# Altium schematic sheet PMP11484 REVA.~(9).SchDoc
size 431 x 279 mm; Date: Not shown in title block; ApprovedBy: Not shown in title block; CheckedBy: Not shown in title block; Author: Not shown in title block; CompanyName: Not shown in title block; Engineer: Not shown in title block; Organization: Not shown in title block; Address1: Not shown in title block; Address2: Not shown in title block; Address3: Not shown in title block; Address4: Not shown in title block; DocumentNumber: 1; Revision: Use project parameter SCH_Rev; SheetNumber: 1; SheetTotal: 1; PageSetup: Record=PageOptions¦CenterHorizontal=True¦CenterVertical=True¦PrintScale=1.00¦XCorrection=1.00¦YCorrection=1.00¦PrintKind=0¦BorderSize=5000000¦LeftOffset=0¦BottomOffset=0¦Orientation=2¦PaperLength=1000¦PaperWidth=1000¦Scale=100¦PaperSource=15¦PrintQuality=600¦MediaType=1¦DitherType=10¦PaperKind=Letter¦PrintScaleMode=1
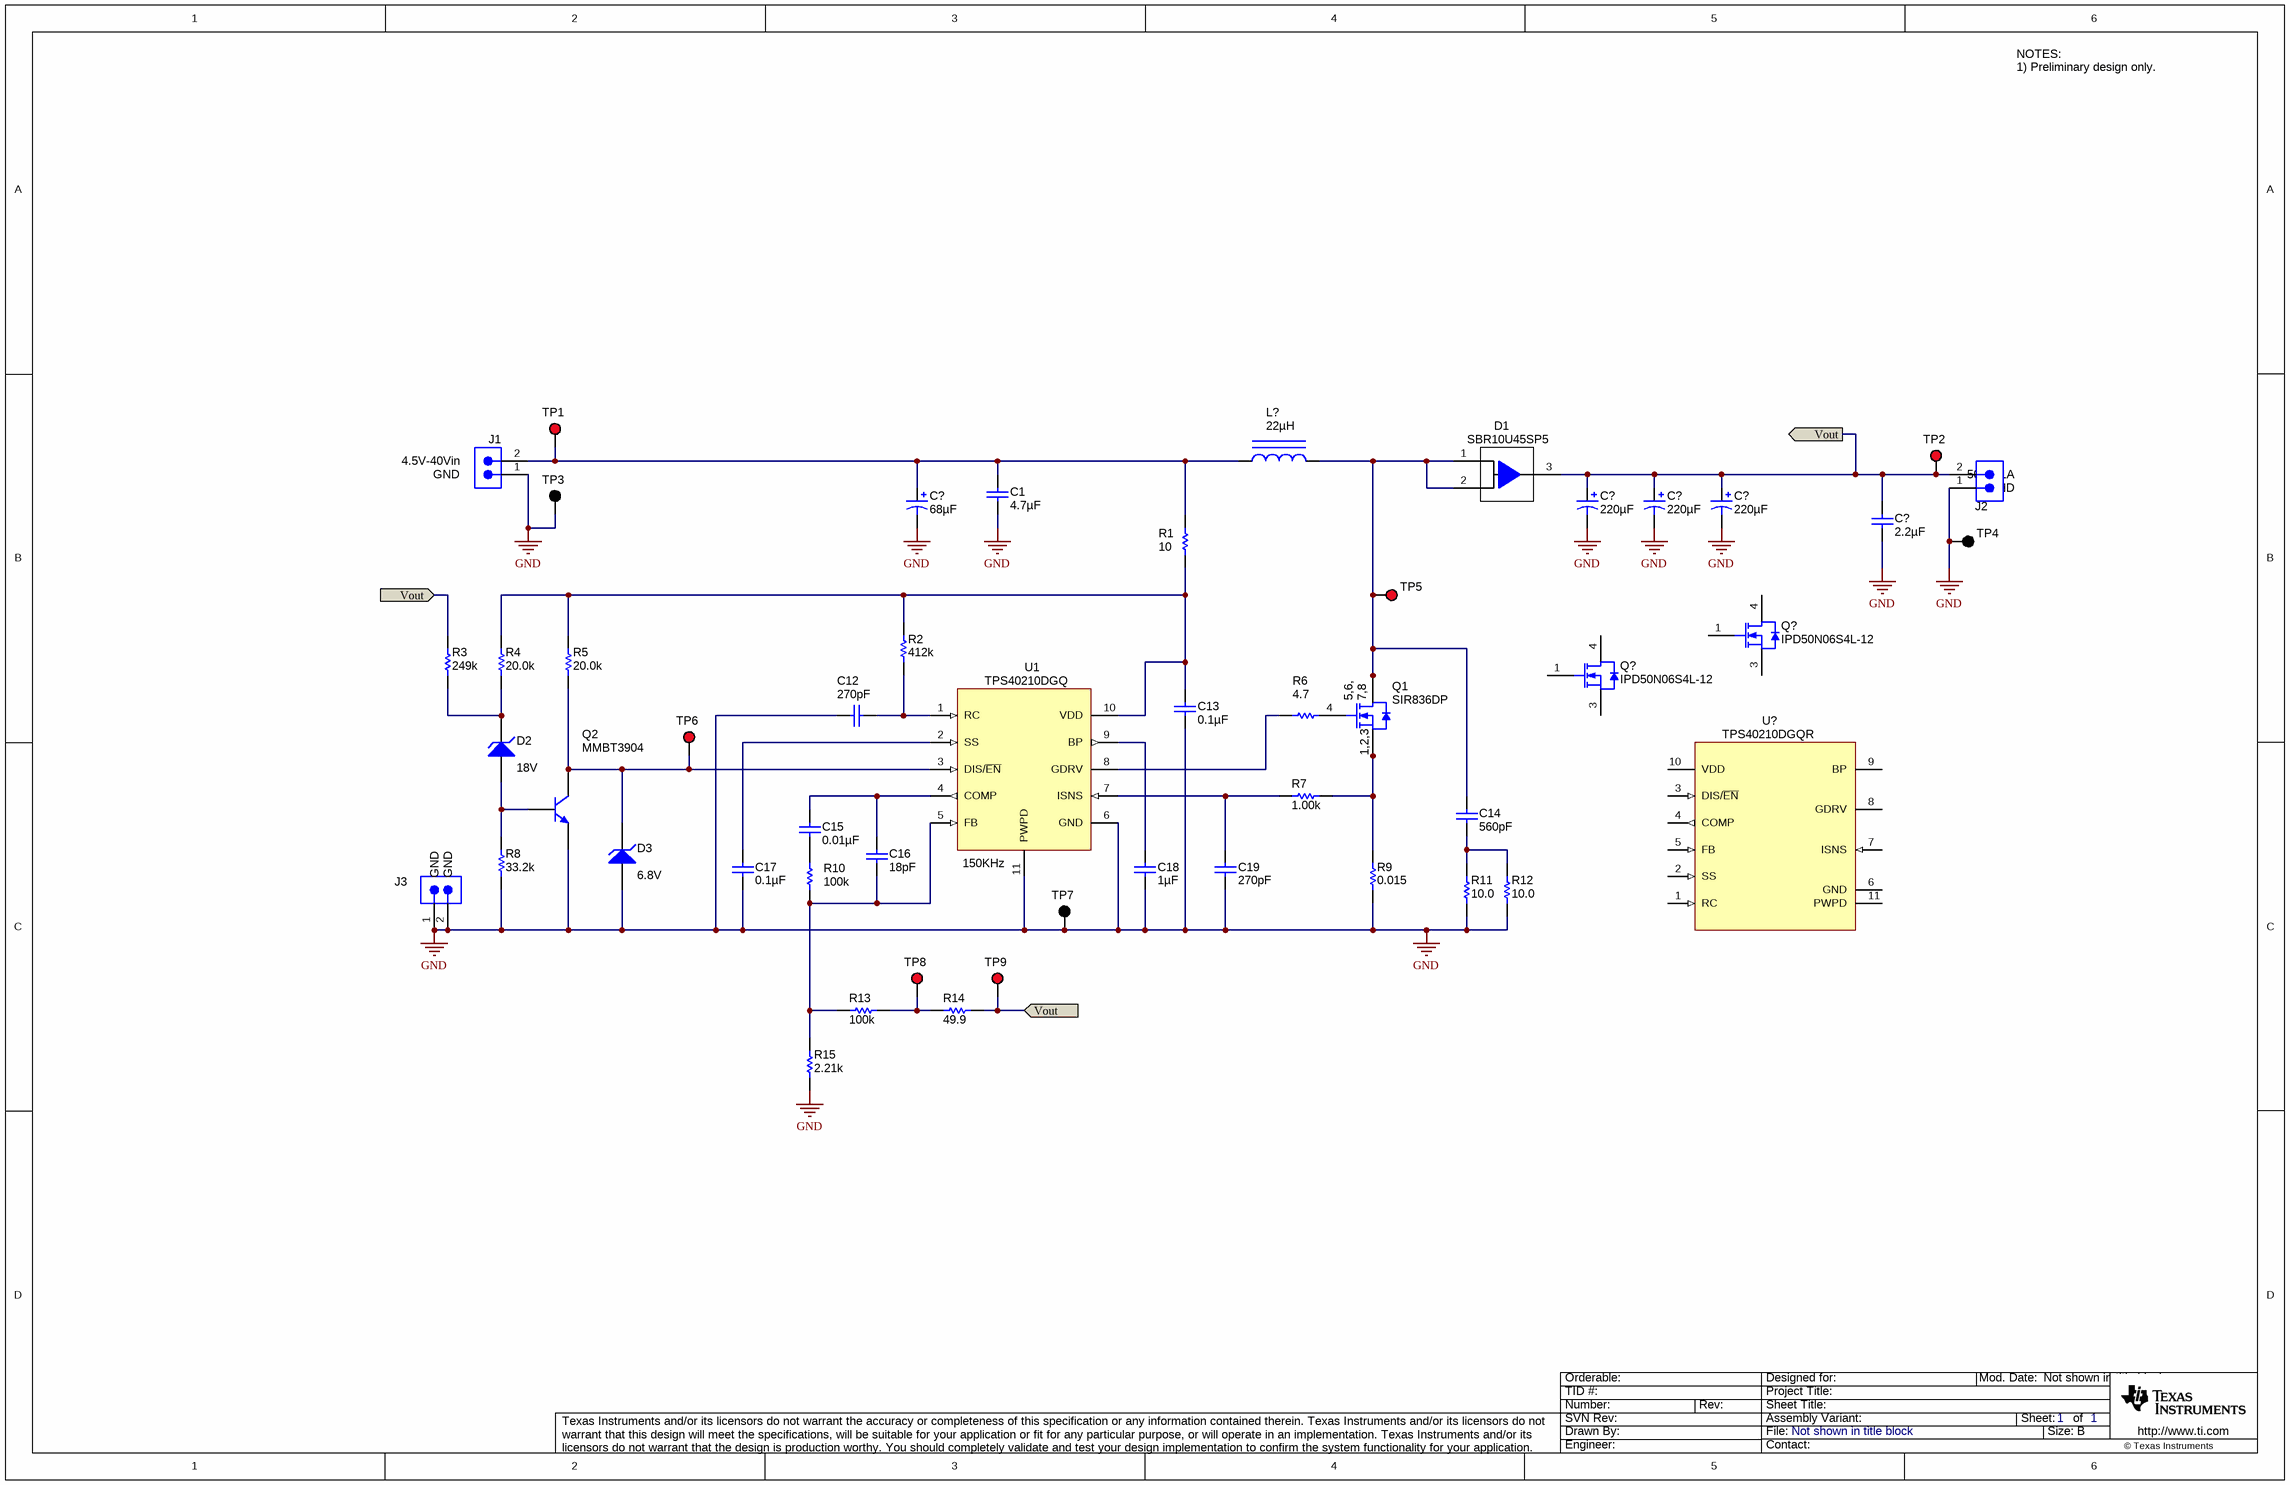
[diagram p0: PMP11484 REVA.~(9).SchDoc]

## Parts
(Parts that share a designator on the sheet are numbered #1, #2 ... from top to bottom, then left to right.)
C1  ValueDisplayed: 4.7µF  [1210]  (hidden comment: C3225X7R1H475M250AB)
C12  ValueDisplayed: 270pF  [0603]  (hidden comment: GRM1885C1H271JA01D)
C13  ValueDisplayed: 0.1µF  [0603]  (hidden comment: C1608X7R1H104K)
C14  ValueDisplayed: 560pF  [0603]  (hidden comment: C1608C0G1H561J)
C15  ValueDisplayed: 0.01µF  [0603]  (hidden comment: C1608X7R1H103K)
C16  ValueDisplayed: 18pF  [0603]  (hidden comment: C1608C0G1H180J)
C17  ValueDisplayed: 0.1µF  [0603]  (hidden comment: C1608X7R1H104K)
C18  ValueDisplayed: 1µF  [0603]  (hidden comment: C1608X7R1C105K)
C19  ValueDisplayed: 270pF  [0603]  (hidden comment: GRM1885C1H271JA01D)
C?#1  ValueDisplayed: 68µF  [SM_RADIAL_8MM]  (hidden comment: EEHZA1H680P)
C?#2  ValueDisplayed: 220µF  [BT_1250x2500]  (hidden comment: UBT1K221MHD1TO)
C?#3  ValueDisplayed: 220µF  [BT_1250x2500]  (hidden comment: UBT1K221MHD1TO)
C?#4  ValueDisplayed: 220µF  [BT_1250x2500]  (hidden comment: UBT1K221MHD1TO)
C?#5  ValueDisplayed: 2.2µF  [1210]  (hidden comment: GRM32ER72A225KA35L)
D1  SBR10U45SP5  [PowerDI5]
D2  value 18V  [SOD-123]  (hidden comment: MMSZ5248B)
D3  value 6.8V  [SOD-123]  (hidden comment: MMSZ5235B)
J1  ED555/2DS  [TERM_BLK_ED555-2DS]  (value not drawn)
J2  ED555/2DS  [TERM_BLK_ED555-2DS]  (value not drawn)
J3  PEC02SAAN  [CONN_PEC02SAAN]  (value not drawn)
L?  ValueDisplayed: 22µH  [IHLP8787MZ]  (hidden comment: IHLP8787MZER220M5A)
Q1  SIR836DP  [PowerPAK_SO-8]
Q2  MMBT3904  [SOT-23]
Q?#1  IPD50N06S4L-12  [DPAK]
Q?#2  IPD50N06S4L-12  [DPAK]
R1  value 10  [0603]  (hidden comment: CRCW060310R0JNEA)
R2  ValueDisplayed: 412k  [0603]  (hidden comment: CRCW0603412KFKEA)
R3  value 249k  [0603]  (hidden comment: CRCW0603249KFKEA)
R4  value 20.0k  [0603]  (hidden comment: CRCW060320K0FKEA)
R5  value 20.0k  [0603]  (hidden comment: CRCW060320K0FKEA)
R6  value 4.7  [0603]  (hidden comment: CRCW06034R70JNEA)
R7  value 1.00k  [0603]  (hidden comment: CRCW06031K00FKEA)
R8  value 33.2k  [0603]  (hidden comment: CRCW060333K2FKEA)
R9  value 0.015  [1206]  (hidden comment: CSR1206FK15L0)
R10  value 100k  [0603]  (hidden comment: CRCW0603100KFKEA)
R11  value 10.0  [1206]  (hidden comment: CRCW120610R0FKEA)
R12  value 10.0  [1206]  (hidden comment: CRCW120610R0FKEA)
R13  value 100k  [0603]  (hidden comment: CRCW0603100KFKEA)
R14  value 49.9  [0603]  (hidden comment: CRCW060349R9FKEA)
R15  value 2.21k  [0603]  (hidden comment: CRCW06032K21FKEA)
TP1  5000  [Keystone5000]  (value not drawn)
TP2  5000  [Keystone5000]  (value not drawn)
TP3  5001  [Keystone5001]  (value not drawn)
TP4  5001  [Keystone5001]  (value not drawn)
TP5  5000  [Keystone5000]  (value not drawn)
TP6  5000  [Keystone5000]  (value not drawn)
TP7  5001  [Keystone5001]  (value not drawn)
TP8  5000  [Keystone5000]  (value not drawn)
TP9  5000  [Keystone5000]  (value not drawn)
U1  TPS40210DGQ  [DGQ0010D_N]
U?  TPS40210DGQR  [DGQ0010D_N]

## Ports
Vout

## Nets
GND: C1.1 C12.1 C13.2 C17.2 C18.2 C19.2 C?#1.2(-) C?#2.2(-) C?#3.2(-) C?#4.2(-) C?#5.2 D3.2(A) J1.1 J2.1 J3.1 J3.2 Q2.2(E) R8.1 R9.1 R11.1 R12.1 R15.1 TP3.1 TP4.1 TP7.1 U1.6(GND) U1.11(PWPD)
Vout: C?#2.1(+) C?#3.1(+) C?#4.1(+) C?#5.1 D1.3(K) J2.2 R3.2 R14.1 TP2.1 TP9.1 ; port Vout
NetC1_2: C1.2 C?#1.1(+) J1.2 L?.1 R1.2 TP1.1
NetC12_2: C12.2 R2.1 U1.1(RC)
NetC13_1: C13.1 R1.1 R2.2 R4.2 R5.2 U1.10(VDD)
NetC14_1: C14.1 R11.2 R12.2
NetC14_2: C14.2 D1.1(A) D1.2(A) L?.2 Q1.5(D) Q1.6(D) Q1.7(D) Q1.8(D) Q1.9(D) TP5.1
NetC15_1: C15.1 R10.1
NetC15_2: C15.2 C16.2 U1.4(COMP)
NetC16_1: C16.1 R10.2 R13.2 R15.2 U1.5(FB)
NetC17_1: C17.1 U1.2(SS)
NetC18_1: C18.1 U1.9(BP)
NetC19_1: C19.1 R7.2 U1.7(ISNS)
NetD2_1: D2.1(K) R3.1 R4.1
NetD2_2: D2.2(A) Q2.1(B) R8.2
NetD3_1: D3.1(K) Q2.3(C) R5.1 TP6.1 U1.3(DIS/~{EN})
NetQ1_1: Q1.1(S) Q1.2(S) Q1.3(S) R7.1 R9.2
NetQ1_4: Q1.4(G) R6.2
NetR6_1: R6.1 U1.8(GDRV)
NetR13_1: R13.1 R14.2 TP8.1

Not connected (* = marked no-connect by the designer): Q?#1 1(G) 3(S) 4(D); Q?#2 1(G) 3(S) 4(D); U? 1(RC) 2(SS) 3(DIS/~{EN}) 4(COMP) 5(FB) 6(GND) 7(ISNS) 8(GDRV) 9(BP) 10(VDD) 11(PWPD)

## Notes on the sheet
- NOTES:
  1) Preliminary design only.
- (near J1) 4.5V-40Vin
- (near J1) GND
- (near J2) 50V@1A
- (near J2) GND
- (near J3) GND
- GND
- (near U1) 150KHz

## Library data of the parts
C1 = C3225X7R1H335M: CAP, CERM, 4.7uF, 50V, +/-20%, X7R, 1210; Manufacturer: TDK; Polarized: N; CompType: Capacitor; U/M: EA; Cap_F: 0.0000033; Tolerance_%: 20; Value1: Unknown; VDC_V: 50; TaMin_C: -55; TaMax_C: 125
C12 C19 = GRM1885C1H271JA01D: CAP, CERM, 270pF, 50V, +/-5%, C0G/NP0, 0603; Manufacturer: MuRata; Polarized: N; CompType: Capacitor; U/M: EA; Cap_F: 0.00000000027; Tolerance_%: 5; Value1: Unknown; VDC_V: 50; TaMin_C: -55; TaMax_C: 125
C13 C17 = C1608X7R1H104K: CAP, CERM, 0.1uF, 50V, +/-10%, X7R, 0603; Manufacturer: TDK; Polarized: N; CompType: Capacitor; U/M: EA; Cap_F: 0.0000001; Tolerance_%: 10; ESR_Ohm: 0.017; Value1: 0.017 ohm; VDC_V: 50; TaMin_C: -55; TaMax_C: 125
C14 = C1608C0G1H561J: CAP, CERM, 560pF, 50V, +/-5%, C0G/NP0, 0603; Manufacturer: TDK; Polarized: N; CompType: Capacitor; U/M: EA; Cap_F: 0.00000000056; Tolerance_%: 5; ESR_Ohm: 0.0858; Value1: 0.0858 ohm; VDC_V: 50; TaMin_C: -55; TaMax_C: 125
C15 = C1608X7R1H103K: CAP, CERM, 0.01uF, 50V, +/-10%, X7R, 0603; Manufacturer: TDK; Polarized: N; CompType: Capacitor; U/M: EA; Cap_F: 0.00000001; Tolerance_%: 10; ESR_Ohm: 0.0539; Value1: 0.0539 ohm; VDC_V: 50; TaMin_C: -55; TaMax_C: 125
C16 = C1608C0G1H180J: CAP, CERM, 18pF, 50V, +/-5%, C0G/NP0, 0603; Manufacturer: TDK; Polarized: N; CompType: Capacitor; U/M: EA; Cap_F: 0.000000000018; Tolerance_%: 5; ESR_Ohm: 0.4028; Value1: 0.4028 ohm; VDC_V: 50; TaMin_C: -55; TaMax_C: 125
C18 = C1608X7R1C105K: CAP, CERM, 1uF, 16V, +/-10%, X7R, 0603; Manufacturer: TDK; Polarized: N; CompType: Capacitor; U/M: EA; Cap_F: 0.000001; Tolerance_%: 10; ESR_Ohm: 0.0057; Value1: 0.0057 ohm; VDC_V: 16; TaMin_C: -55; TaMax_C: 125
C?#1 = EEHZA1H680P: CAP, Polymer Hybrid, 68 µF, 50 V, +/- 20%, 30 ohm, 8x10 SMD; Manufacturer: Panasonic; Polarized: Y; CompType: Capacitor; Value: 68uF; U/M: EA; Cap_F: 0.000068; Tolerance_%: 20; Value1: 30 ohm; VDC_V: 50; Value2: 50V; ESR_ohm: 30; IRMS_A: 1.8; TaMin_C: -55; TaMax_C: 105; AEC Category: Q200
C?#2-C?#4 = UBT1H471MHD1TO: CAP, AL, 470 µF, 80 V, +/- 20%, 0.180 ohm, 1.24A, AEC-Q200 Grade 1, TH; Manufacturer: Nichicon; Polarized: Y; CompType: Capacitor; Value: 220uF; U/M: EA; Cap_F: 0.00047; Tolerance_%: 20; VDC_V: 80; Value2: 80V; TaMin_C: -40; TaMax_C: 125; Cap_Case: 12.5x25mm; AEC Category: Q200; AEC Grade: 1
C?#5 = GRM32ER72A225KA35L: CAP, CERM, 2.2 µF, 100 V, +/- 10%, X7R, 1210; Manufacturer: MuRata; Polarized: N; CompType: Capacitor; Value: 2.2uF; U/M: EA; Cap_F: 0.0000022; Tolerance_%: 10; ESR_ohm: 0.007; Value1: 0.007 ohm; VDC_V: 100; Value2: 100V; IRMS_A: 4.4; TaMin_C: -55; TaMax_C: 125; AEC Category: Q200
D1 = SBR10U45SP5: Diode, Super Barrier Rectifier, 45V, 10A, PowerDI5; Manufacturer: Diodes Inc.; SymbolCreator: a0412235; U/M: EA; Vf_V: 0.47; Value2: 0.47V; Io_A: 10; Vr_V: 45; TJmax_C: 150
D2 = MMSZ5248B-7-F: Diode, Zener, 18V, 500mW, SOD-123; Manufacturer: Diodes Inc.; U/M: EA; Power_W: 0.5; Vz_V: 18; Value1: 0.5W; RJA_CperW: 350
D3 = MMSZ5231B-7-F: Diode, Zener, 6.8V, 500mW, SOD-123; Manufacturer: Diodes Inc.; U/M: EA; Power_W: 0.5; Vz_V: 6.8; Value1: 0.5W; RJA_CperW: 350
J1 J2 = ED555/2DS: Terminal Block, 6A, 3.5mm Pitch, 2-Pos, TH; Manufacturer: On-Shore Technology, Inc.; SymbolCreator: a0412235; CompType: Connector; U/M: EA
J3 = PEC02SAAN: Header, 100mil, 2x1, Tin plated, TH; Manufacturer: Sullins Connector Solutions; SymbolCreator: a0412235; U/M: EA
L? = IHLP8787MZE470M51: Inductor, Shielded, 22 µH, 16 A, 0.0106 ohm, SMD; Manufacturer: Vishay-Dale; Value: 22uH; Value2: 16A
Q1 = SIR836DP-T1-GE3: MOSFET, N-CH, 40V, 21A, PowerPAK SO-8; Manufacturer: Vishay-Siliconix; Alternate Manufacturer: None; U/M: EA; ChType: N; VdsMax_V: 40; Value1: 0.0225 ohm; Rdson45_Ohm: 0.0225; Value2: 5.8 nC; QgTyp_nC: 5.8; Vgs_V: 20; IdsMax_A: 21
Q2 = MMBT3904-7-F, Diodes Inc.: Transistor, NPN, 40V, 0.2A, SOT-23; CompType: BJT; PNP: 0; NPN: 1; Vceo_V: 40; Vcesat1_V: 0.2; Value: 0.2V; HfeMax: 400; TaMin_C: -55; TaMax_C: 150; U/M: EA
Q?#1 Q?#2 = IPD50R280CE: MOSFET, N-CH, 60 V, 0.012 Ohms, AEC-Q101, DPAK; Manufacturer: Infineon Technologies; Alternate Manufacturer: None; U/M: EA; ChType: N; Value: 60V; VdsMax_V: 60; QgTyp_nC: 32.6; Vgs_V: 16; IdsMax_A: 13; AEC Category: Q101
R1 = CRCW060310R0JNEA: RES, 10 ohm, 1%, 0.1W, 0603; Manufacturer: Vishay-Dale; CompType: Resistor; Value_Code: 10R0; Tolerance_%: 5; Power_W: 0.1; VDC_V: 75; TempCo: 200 ppm/C; EIA_Code: E24; U/M: EA
R2 = CRCW0603412KFKEA: RES, 412 k, 1%, 0.1 W, 0603; Manufacturer: Vishay-Dale; CompType: Resistor; Value: 412k; Res_ohm: 412000; Tolerance_%: 1; Power_W: 0.1; Value2: 0.1W; VDC_V: 75; TempCo: 100 ppm/C; EIA_Code: E96; U/M: EA; AEC Category: Q200
R3 = CRCW0603249KFKEA: RES, 249k ohm, 1%, 0.1W, 0603; Manufacturer: Vishay-Dale; CompType: Resistor; Res_ohm: 249000; Tolerance_%: 1; Power_W: 0.1; VDC_V: 75; TempCo: 100 ppm/C; EIA_Code: E96; U/M: EA
R4 R5 = CRCW060320K0FKEA: RES, 20.0k ohm, 1%, 0.1W, 0603; Manufacturer: Vishay-Dale; CompType: Resistor; Res_ohm: 20000; Value_Code: 20k0; Tolerance_%: 1; Power_W: 0.1; VDC_V: 75; TempCo: 100 ppm/C; EIA_Code: E96; U/M: EA
R6 = CRCW06034R70JNEA: RES, 4.7 ohm, 5%, 0.1W, 0603; Manufacturer: Vishay-Dale; CompType: Resistor; Value_Code: 4R70; Tolerance_%: 5; Power_W: 0.1; VDC_V: 75; TempCo: 200 ppm/C; EIA_Code: E24; U/M: EA
R7 = CRCW06031K00FKEA: RES, 1.00k ohm, 1%, 0.1W, 0603; Manufacturer: Vishay-Dale; CompType: Resistor; Res_ohm: 1000; Value_Code: 1k00; Tolerance_%: 1; Power_W: 0.1; VDC_V: 75; TempCo: 100 ppm/C; EIA_Code: E96; U/M: EA
R8 = CRCW060333K2FKEA: RES, 33.2k ohm, 1%, 0.1W, 0603; Manufacturer: Vishay-Dale; CompType: Resistor; Res_ohm: 33200; Value_Code: 33k2; Tolerance_%: 1; Power_W: 0.1; VDC_V: 75; TempCo: 100 ppm/C; EIA_Code: E96; U/M: EA
R9 = CSR1206FK15L0: RES, 0.015 ohm, 1%, 0.5W, 1206; Manufacturer: Stackpole Electronics Inc; CompType: Resistor; Value_Code: R015; Tolerance_%: 1; Power_W: 0.5; TempCo: 100 ppm/C; EIA_Code: E96; U/M: EA
R10 R13 = CRCW0603100KFKEA: RES, 100k ohm, 1%, 0.1W, 0603; Manufacturer: Vishay-Dale; CompType: Resistor; Res_ohm: 100000; Tolerance_%: 1; Power_W: 0.1; VDC_V: 75; TempCo: 100 ppm/C; EIA_Code: E96; U/M: EA
R11 R12 = CRCW120610R0FKEA: RES, 10.0 ohm, 1%, 0.25W, 1206; Manufacturer: Vishay-Dale; CompType: Resistor; Res_ohm: 10; Value_Code: 10R0; Tolerance_%: 1; Power_W: 0.25; VDC_V: 200; TempCo: 100 ppm/C; EIA_Code: E96; U/M: EA
R14 = CRCW060349R9FKEA: RES, 49.9 ohm, 1%, 0.1W, 0603; Manufacturer: Vishay-Dale; CompType: Resistor; Value_Code: 49R9; Tolerance_%: 1; Power_W: 0.1; VDC_V: 75; TempCo: 100 ppm/C; EIA_Code: E96; U/M: EA
R15 = CRCW06032K21FKEA: RES, 2.21k ohm, 1%, 0.1W, 0603; Manufacturer: Vishay-Dale; CompType: Resistor; Res_ohm: 2210; Value_Code: 2k21; Tolerance_%: 1; Power_W: 0.1; VDC_V: 75; TempCo: 100 ppm/C; EIA_Code: E96; U/M: EA
TP1 TP2 TP5 TP6 TP8 TP9 = 5000: Test Point, TH, Miniature, Red; Manufacturer: Keystone; CompType: Test Point Loop; U/M: EA
TP3 TP4 TP7 = 5001: Test Point, TH, Miniature, Black; Manufacturer: Keystone; CompType: Test Point Loop; U/M: EA
U1 = TPS40210DGQ: 4.5-V TO 52-V INPUT CURRENT MODE BOOST CONTROLLER, DGQ0010D; Alternate Manufacturer: None; Manufacturer: Texas Instruments; SymbolCreator: a0412235; CompType: IC; U/M: EA
U? = TPS40210DGQR: 4.5-V TO 52-V INPUT CURRENT MODE BOOST CONTROLLER, DGQ0010D; Manufacturer: Texas Instruments; SymbolCreator: a0412235; CompType: IC; U/M: EA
